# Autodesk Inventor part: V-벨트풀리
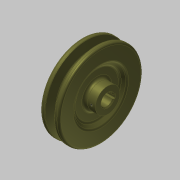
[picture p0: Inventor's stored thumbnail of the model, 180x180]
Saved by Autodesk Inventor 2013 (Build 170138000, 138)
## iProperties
Company: 한국ATC센터
Created: 2015-12
Part Number: V-벨트풀리
Document SubType Name: Modeling
Designer: mdu
Density: 7.25 g/cm^3
Mass: 594.58 g
Surface Area: 210.471 cm^2
Volume: 82.011 cm^3
Material: 주철
Author: mdu
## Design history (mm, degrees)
sketch "스케치1"
  geometry: L1 (-13, 0)-(13, 0); L2 (-13, 0)-(-13, 12.5); L3 (-13, 12.5)-(-9, 12.5); L4 (-9, 12.5)-(-9, 23); L5 (-9, 23)-(-13, 27); L6 (-13, 27)-(-13, 42.7); L7 (-13, 42.7)-(-8.325, 42.7); L8 (-8.325, 42.7)-(-5.574, 33.7); L9 (-5.574, 33.7)-(-1.426, 33.7); L10 (-1.426, 33.7)-(1.325, 42.7); L11 (1.325, 42.7)-(6, 42.7); L12 (6, 42.7)-(6, 27); L13 (6, 27)-(2, 23); L14 (2, 23)-(2, 12.5); L15 (2, 12.5)-(13, 12.5); L16 (13, 12.5)-(13, 0); L17 (-7.5, 40)-(0.5, 40); 2 further points
  constraints: 34 end point, 6 parallel, 5 collinear, 5 equal length, 4 perpendicular, 2 point on line, 1 coincident, 1 horizontal, 1 midpoint
  dimensions: "d0" = 26 distance of L1.start L1.end; "d1" = 2.7 distance between parallel lines of L7 L17; "d2" = 6.3 distance between parallel lines of L9 L17; "d3" = 8 distance of L17.start L17.end; "d4" = 34 deg angle of L10 L8; "d5" = 19 distance between parallel lines of L12 L6; "d7" = 25 diameter of L15 L1; "d8" = 46 diameter of L13.end L1; "d9" = 54 diameter of L12.end L1; "d10" = 4 distance between parallel lines of L2 L4; "d11" = 80 diameter of L17 L1
revolve "회전1" sketch "스케치1" stored, may be unused: angle "d12" = 90 deg
sketch "스케치2"
  geometry: L1 (-2, 5.657)-(-2, 7.8); L2 (-2, 7.8)-(2, 7.8); L3 (2, 7.8)-(2, 5.657); A1 r 6 centre (0, 0) between (-2, 5.657) and (2, 5.657); 1 further point
  constraints: 6 end point, 2 parallel, 2 point on circle, 1 centre point, 1 coincident, 1 perpendicular, 1 vertical
  dimensions: "d13" = 12 diameter of A1; "d14" = 13.8 dimension on A1 L2; "d15" = 4 distance of L1.end L2.end
extrude "돌출1" cut sketch "스케치2" stored distance "d16" = 10; taper "d17" = 0 deg
node "작업 평면1"
sketch "스케치3"
  geometry: L1 (-5.5, 12.5)-(-5.5, -12.5) reference; L2 (20.5, 27)-(20.5, -27) reference; 3 further points
  constraints: 1 horizontal alignment, 1 midpoint
  dimensions: "d18" = 4 distance from line of point (-1.5, 0) L1; "d33" = 22 distance from line of point (-1.5, 0) L2 (derived)
hole "구멍1" sketch "스케치3" at (-1.5, 0) diameter "d19" = 2.459; stored, may be unused: countersink angle "d23" = 90 deg, drill point angle "d25" = 118 deg; dims "d20" = 6, "d21" = 4, "d22" = 2, "d24" = 8
fillet "모깎기1" dims "d26" = 2, "d27" = 0.5, "d28" = 1, "d29" = 3
chamfer "모따기1" distance "d30" = 1; stored, may be unused: second distance "d31" = 2, angle "d32" = 45 deg
sketch "스케치4" dims "d35" = 70
  geometry: C1 r 3 at (0, 35); 2 further points
  constraints: 2 vertical alignment, 1 centre point, 1 coincident, 2 other
  dimensions: "d34" = 6 diameter of C1
extrude "돌출2" join sketch "스케치4" distance "d36" = 10; taper "d37" = 0 deg
fillet "모깎기2" dims "d38" = 0.5, "d39" = 1
node "솔리드1"
